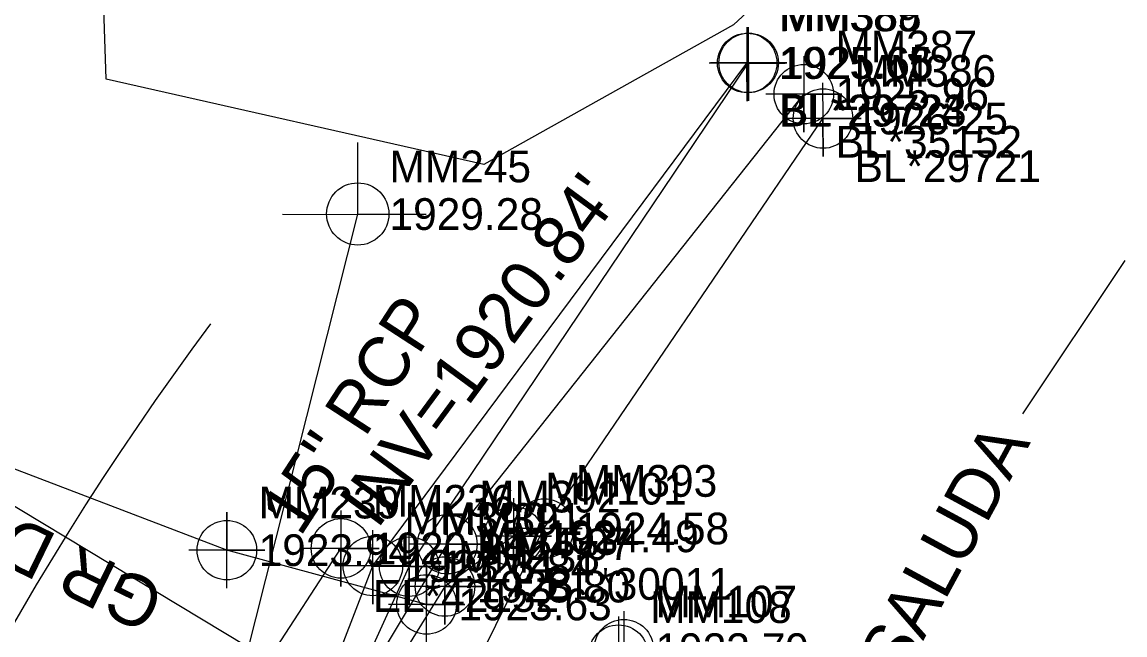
# Model space of a CAD drawing. Extents: x 1004514 to 1005247, y 553695 to 554706.
# Drawn here: x 1005003.6 to 1005090.5, y 554259.6 to 554307.9 of the extents above; entities that cross this region are included whole.
import ezdxf

# ---------------------------------------------------------------- set-up
doc = ezdxf.new("R2010")
doc.units = 0
for name, color, linetype in [('Exist DTM Crownline Cogo Elevation', 7, 'Continuous'), ('Exist DTM Crownline Cogo Number', 7, 'Continuous'), ('Exist DTM Crownline Cogo Point CELL', 7, 'Continuous'), ('Exist Right of Way Line', 7, 'Continuous'), ('Exist Roads EOP', 7, 'Continuous'), ('Exist Roads EOP Cogo Comment', 7, 'Continuous'), ('Exist Roads EOP Cogo Elevation', 7, 'Continuous'), ('Exist Roads EOP Cogo Number', 7, 'Continuous'), ('Exist Roads EOP Cogo Point CELL', 7, 'Continuous'), ('Exist Roads EOP Leader', 7, 'Continuous'), ('Exist Roads EOP Text', 7, 'Continuous'), ('Exist Roads Soil', 7, 'Continuous'), ('Exist Roads Soil Cogo Elevation', 7, 'Continuous'), ('Exist Roads Soil Cogo Number', 7, 'Continuous'), ('Exist Roads Soil Cogo Point CELL', 7, 'Continuous'), ('Exist Roads Soil Text', 7, 'Continuous'), ('Exist Structure Minor Pipes RCP 15 Inch', 7, 'Continuous'), ('Exist Structure Minor Pipes RCP 15 Inch Cogo Comment', 7, 'Continuous'), ('Exist Structure Minor Pipes RCP 15 Inch Cogo Elevation', 7, 'Continuous'), ('Exist Structure Minor Pipes RCP 15 Inch Cogo Number', 7, 'Continuous'), ('Exist Structure Minor Pipes RCP 15 Inch Cogo Point CELL', 7, 'Continuous'), ('Exist Structure Minor Pipes RCP 15 Inch Invert', 7, 'Continuous'), ('Exist Structure Minor Pipes RCP 15 Inch Text', 7, 'Continuous'), ('Exist Utilities Power Joint Use Telephone CELL', 7, 'Continuous'), ('Exist Utilities Power Joint Use Telephone Cogo Elevation', 7, 'Continuous'), ('Exist Utilities Power Joint Use Telephone Cogo Number', 7, 'Continuous'), ('Exist Utilities Telephone UG Conduit SUE LOS B', 7, 'Continuous'), ('Exist Utilities Telephone UG Conduit SUE LOS B Cogo Comment', 7, 'Continuous'), ('Exist Utilities Telephone UG Conduit SUE LOS B Cogo Elevation', 7, 'Continuous'), ('Exist Utilities Telephone UG Conduit SUE LOS B Cogo Number', 7, 'Continuous'), ('Exist Utilities Telephone UG Conduit SUE LOS B Cogo Point CELL', 7, 'Continuous'), ('Exist Utilities Telephone UG FO SUE LOS C', 7, 'Continuous'), ('Exist Utilities Telephone UG FO SUE LOS C Cogo Comment', 7, 'Continuous'), ('Exist Utilities Telephone UG FO SUE LOS C Cogo Elevation', 7, 'Continuous'), ('Exist Utilities Telephone UG FO SUE LOS C Cogo Number', 7, 'Continuous'), ('Exist Utilities Telephone UG FO SUE LOS C Cogo Point CELL', 7, 'Continuous'), ('Exist Vegetation Woods Line', 7, 'Continuous'), ('Old_Level_3', 7, 'Continuous'), ('Scratch_Level_3', 7, 'Continuous')]:
    doc.layers.add(name, color=color, linetype=linetype)

msp = doc.modelspace()

# ---------------------------------------------------------------- linework, layer by layer
at = {"layer": 'Exist DTM Crownline Cogo Point CELL'}
for points in [[(1005051.005, 554261.476), (1005051.005, 554255.476), (1005051.005, 554258.476), (1005054.005, 554258.476), (1005048.005, 554258.476)], [(1005050.587, 554261.044), (1005050.587, 554255.044), (1005050.587, 554258.044), (1005053.587, 554258.044), (1005047.587, 554258.044)]]:
    msp.add_lwpolyline(points, dxfattribs=at)
for centre in [(1005050.587, 554258.044), (1005051.005, 554258.476)]:
    msp.add_circle(centre, 2.344, dxfattribs=at)
at = {"layer": 'Exist Right of Way Line'}
msp.add_arc((1005209.198, 554141.741), 238, 143.26447, 181.15854, dxfattribs=at)
at = {"layer": 'Exist Roads EOP'}
msp.add_lwpolyline([(1005042.326, 554267.369), (1005036.922, 554263.41), (1005028.544, 554249.886), (1005026.381, 554243.671)], dxfattribs=at)
at = {"layer": 'Exist Roads EOP Cogo Point CELL'}
for points in [[(1005042.326, 554270.369), (1005042.326, 554264.369), (1005042.326, 554267.369), (1005045.326, 554267.369), (1005039.326, 554267.369)], [(1005036.922, 554266.41), (1005036.922, 554260.41), (1005036.922, 554263.41), (1005039.922, 554263.41), (1005033.922, 554263.41)]]:
    msp.add_lwpolyline(points, dxfattribs=at)
for centre in [(1005042.326, 554267.369), (1005036.922, 554263.41)]:
    msp.add_circle(centre, 2.344, dxfattribs=at)
at = {"layer": 'Exist Roads EOP Leader'}
msp.add_line((1005090.478, 554289.095), (1005082.421, 554277.008), dxfattribs=at)
at = {"layer": 'Exist Roads Soil'}
msp.add_lwpolyline([(1005035.476, 554262.003), (1005019.749, 554266.277), (1004983.505, 554280.108), (1004961.55, 554283.385)], dxfattribs=at)
at = {"layer": 'Exist Roads Soil Cogo Point CELL'}
for points in [[(1005019.749, 554263.277), (1005019.749, 554269.277), (1005019.749, 554266.277), (1005022.749, 554266.277), (1005016.749, 554266.277)], [(1005035.476, 554259.003), (1005035.476, 554265.003), (1005035.476, 554262.003), (1005038.476, 554262.003), (1005032.476, 554262.003)]]:
    msp.add_lwpolyline(points, dxfattribs=at)
for centre in [(1005019.749, 554266.277), (1005035.476, 554262.003)]:
    msp.add_circle(centre, 2.344, dxfattribs=at)
at = {"layer": 'Exist Structure Minor Pipes RCP 15 Inch'}
msp.add_line((1005014.54, 554244.581), (1005028.734, 554266.415), dxfattribs=at)
at = {"layer": 'Exist Structure Minor Pipes RCP 15 Inch Cogo Point CELL'}
msp.add_lwpolyline([(1005028.734, 554269.415), (1005028.734, 554263.415), (1005028.734, 554266.415), (1005031.734, 554266.415), (1005025.734, 554266.415)], dxfattribs=at)
msp.add_circle((1005028.734, 554266.415), 2.344, dxfattribs=at)
at = {"layer": 'Exist Utilities Power Joint Use Telephone CELL'}
msp.add_line((1005030.054, 554292.752), (1005030.054, 554292.752), dxfattribs=at)
msp.add_lwpolyline([(1005024.116, 554292.752), (1005035.454, 554292.714), (1005030.054, 554292.732), (1005030.054, 554298.377)], dxfattribs=at)
msp.add_circle((1005030.055, 554292.758), 2.45, dxfattribs=at)
at = {"layer": 'Exist Utilities Telephone UG Conduit SUE LOS B'}
for points in [[(1004986.625, 553881.898), (1004994.172, 553936.442), (1004994.355, 553983.339), (1004992.834, 554032.196), (1004992.187, 554082.209), (1005000.242, 554139.11), (1005002.91, 554167.939), (1005012.741, 554216.936), (1005031.231, 554265.036), (1005060.708, 554304.647)], [(1004986.909, 553881.957), (1004994.669, 553936.387), (1004995.066, 553983.404), (1004993.502, 554032.182), (1004992.704, 554081.89), (1004999.846, 554139.17), (1005002.6, 554167.938), (1005012.391, 554217.264), (1005034.093, 554264.981), (1005060.823, 554304.66)], [(1004996.466, 553880.309), (1005003.636, 553934.419), (1005005.075, 553983.38), (1005003.635, 554031.726), (1005001.159, 554081.826), (1005001.307, 554137.229), (1005005.127, 554167.881), (1005016.898, 554214.508), (1005037.162, 554252.759), (1005044.72, 554267.983), (1005066.683, 554300.275)]]:
    msp.add_lwpolyline(points, dxfattribs=at)
at = {"layer": 'Exist Utilities Telephone UG Conduit SUE LOS B Cogo Point CELL'}
for points in [[(1005060.692, 554307.461), (1005060.725, 554301.647), (1005060.708, 554304.647), (1005063.725, 554304.647), (1005057.725, 554304.647)], [(1005060.807, 554307.474), (1005060.84, 554301.66), (1005060.823, 554304.66), (1005063.84, 554304.66), (1005057.84, 554304.66)], [(1005066.667, 554303.09), (1005066.7, 554297.275), (1005066.683, 554300.275), (1005069.7, 554300.275), (1005063.7, 554300.275)], [(1005044.704, 554270.798), (1005044.737, 554264.983), (1005044.72, 554267.983), (1005047.737, 554267.983), (1005041.737, 554267.983)], [(1005031.215, 554267.851), (1005031.248, 554262.036), (1005031.231, 554265.036), (1005034.248, 554265.036), (1005028.248, 554265.036)], [(1005034.077, 554267.796), (1005034.11, 554261.981), (1005034.093, 554264.981), (1005037.11, 554264.981), (1005031.11, 554264.981)]]:
    msp.add_lwpolyline(points, dxfattribs=at)
for centre in [(1005060.725, 554304.647), (1005060.84, 554304.66), (1005066.7, 554300.275), (1005044.737, 554267.983), (1005031.248, 554265.036), (1005034.11, 554264.981)]:
    msp.add_circle(centre, 2.344, dxfattribs=at)
at = {"layer": 'Exist Utilities Telephone UG FO SUE LOS C'}
msp.add_lwpolyline([(1004993.352, 553880.974), (1004999.906, 553935.306), (1005000.501, 553983.286), (1004999.325, 554031.271), (1004996.571, 554081.46), (1004996.427, 554140.051), (1004998.713, 554168.32), (1005009.154, 554220.252), (1005037.109, 554266.749), (1005065.185, 554302.194)], dxfattribs=at)
at = {"layer": 'Exist Utilities Telephone UG FO SUE LOS C Cogo Point CELL'}
for points in [[(1005065.185, 554305.194), (1005065.185, 554299.194), (1005065.185, 554302.194), (1005068.185, 554302.194), (1005062.185, 554302.194)], [(1005037.109, 554269.749), (1005037.109, 554263.749), (1005037.109, 554266.749), (1005040.109, 554266.749), (1005034.109, 554266.749)]]:
    msp.add_lwpolyline(points, dxfattribs=at)
for centre in [(1005065.185, 554302.194), (1005037.109, 554266.749)]:
    msp.add_circle(centre, 2.344, dxfattribs=at)
at = {"layer": 'Exist Vegetation Woods Line'}
msp.add_lwpolyline([(1005081.398, 554327.827), (1005059.657, 554307.666), (1005039.985, 554296.655), (1005010.232, 554303.381), (1005009.969, 554311.341), (1005010.972, 554317.297), (1005030.885, 554314.17), (1005041.105, 554315.294), (1005053.5, 554324.515), (1005054.072, 554342.249), (1005083.847, 554341.701), (1005081.398, 554327.827)], dxfattribs=at)
at = {"layer": 'Old_Level_3'}
msp.add_line((1004974.392, 554286.954), (1005076.106, 554225.778), dxfattribs=at)
at = {"layer": 'Scratch_Level_3'}
msp.add_line((1004952.617, 553985.711), (1005030.054, 554292.752), dxfattribs=at)

# ---------------------------------------------------------------- texts
at = {"layer": 'Exist DTM Crownline Cogo Elevation'}
msp.add_text('1923.79', height=2.5, dxfattribs=at).set_placement((1005053.505, 554257.226))
at = {"layer": 'Exist DTM Crownline Cogo Number'}
for s, p in [('MM108', (1005053.087, 554260.544)), ('MM107', (1005053.505, 554260.976))]:
    msp.add_text(s, height=2.5, dxfattribs=at).set_placement(p)
at = {"layer": 'Exist Roads EOP Cogo Comment'}
msp.add_text('BL*30011', height=2.5, dxfattribs=at).set_placement((1005044.826, 554262.369))
at = {"layer": 'Exist Roads EOP Cogo Elevation'}
for s, p in [('1924.49', (1005044.826, 554266.119)), ('1923.80', (1005039.422, 554262.16))]:
    msp.add_text(s, height=2.5, dxfattribs=at).set_placement(p)
at = {"layer": 'Exist Roads EOP Cogo Number'}
for s, p in [('MM101', (1005044.826, 554269.869)), ('MM103', (1005039.422, 554265.91))]:
    msp.add_text(s, height=2.5, dxfattribs=at).set_placement(p)
at = {"layer": 'Exist Roads EOP Text'}
msp.add_text('TO SALUDA', height=4, rotation=61.53119, dxfattribs=at).set_placement((1005068.629, 554248.128))
at = {"layer": 'Exist Roads Soil Cogo Elevation'}
for s, p in [('1923.94', (1005022.249, 554265.027)), ('1923.63', (1005037.976, 554260.753))]:
    msp.add_text(s, height=2.5, dxfattribs=at).set_placement(p)
at = {"layer": 'Exist Roads Soil Cogo Number'}
for s, p in [('MM239', (1005022.249, 554268.777)), ('MM238', (1005037.976, 554264.503))]:
    msp.add_text(s, height=2.5, dxfattribs=at).set_placement(p)
at = {"layer": 'Exist Roads Soil Text'}
msp.add_text('GR DR', height=4, rotation=154.06895, dxfattribs=at).set_placement((1005015.087, 554263.249))
at = {"layer": 'Exist Structure Minor Pipes RCP 15 Inch Cogo Comment'}
msp.add_text('EL*42152', height=2.5, dxfattribs=at).set_placement((1005031.234, 554261.415))
at = {"layer": 'Exist Structure Minor Pipes RCP 15 Inch Cogo Elevation'}
msp.add_text('1920.84', height=2.5, dxfattribs=at).set_placement((1005031.234, 554265.165))
at = {"layer": 'Exist Structure Minor Pipes RCP 15 Inch Cogo Number'}
msp.add_text('MM236', height=2.5, dxfattribs=at).set_placement((1005031.234, 554268.915))
at = {"layer": 'Exist Structure Minor Pipes RCP 15 Inch Invert'}
for s, rotation, p in [("INV=1920.84'", 53.62823, (1005031.582, 554267.843)), ("INV=1919.20'", 153.00037, (1005016.168, 554251.237))]:
    msp.add_text(s, height=4, rotation=rotation, dxfattribs=at).set_placement(p)
at = {"layer": 'Exist Structure Minor Pipes RCP 15 Inch Text'}
msp.add_text('15" RCP', height=4, rotation=56.97332, dxfattribs=at).set_placement((1005025.519, 554267.248))
at = {"layer": 'Exist Utilities Power Joint Use Telephone Cogo Elevation'}
msp.add_text('1929.28', height=2.5, dxfattribs=at).set_placement((1005032.554, 554291.502))
at = {"layer": 'Exist Utilities Power Joint Use Telephone Cogo Number'}
msp.add_text('MM245', height=2.5, dxfattribs=at).set_placement((1005032.554, 554295.252))
at = {"layer": 'Exist Utilities Telephone UG Conduit SUE LOS B Cogo Comment'}
for s, p in [('BL*29724', (1005063.208, 554299.647)), ('BL*29723', (1005063.323, 554299.66)), ('BL*29721', (1005069.183, 554295.275))]:
    msp.add_text(s, height=2.5, dxfattribs=at).set_placement(p)
at = {"layer": 'Exist Utilities Telephone UG Conduit SUE LOS B Cogo Elevation'}
for s, p in [('1925.65', (1005063.208, 554303.397)), ('1925.66', (1005063.323, 554303.41)), ('1926.25', (1005069.183, 554299.025)), ('1924.58', (1005047.22, 554266.733)), ('1923.61', (1005033.731, 554263.786)), ('1923.84', (1005036.593, 554263.731))]:
    msp.add_text(s, height=2.5, dxfattribs=at).set_placement(p)
at = {"layer": 'Exist Utilities Telephone UG Conduit SUE LOS B Cogo Number'}
for s, p in [('MM389', (1005063.208, 554307.147)), ('MM388', (1005063.323, 554307.16)), ('MM386', (1005069.183, 554302.775)), ('MM393', (1005047.22, 554270.483)), ('MM390', (1005033.731, 554267.536)), ('MM391', (1005036.593, 554267.481))]:
    msp.add_text(s, height=2.5, dxfattribs=at).set_placement(p)
at = {"layer": 'Exist Utilities Telephone UG FO SUE LOS C Cogo Comment'}
msp.add_text('BL*35152', height=2.5, dxfattribs=at).set_placement((1005067.685, 554297.194))
at = {"layer": 'Exist Utilities Telephone UG FO SUE LOS C Cogo Elevation'}
for s, p in [('1925.96', (1005067.685, 554300.944)), ('1924.07', (1005039.609, 554265.499))]:
    msp.add_text(s, height=2.5, dxfattribs=at).set_placement(p)
at = {"layer": 'Exist Utilities Telephone UG FO SUE LOS C Cogo Number'}
for s, p in [('MM387', (1005067.685, 554304.694)), ('MM392', (1005039.609, 554269.249))]:
    msp.add_text(s, height=2.5, dxfattribs=at).set_placement(p)

doc.saveas('drawing.dxf')
